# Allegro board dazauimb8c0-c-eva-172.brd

Outline 219.8 x 128 mm; copper layers: TOP, SGND, IN1, IN2, SVCC, IN3, SGND1, BOTTOM. Coordinates in mm from the lower left corner of the outline.

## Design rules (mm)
constraint set DEFAULT: min track width 0.102
net group W7-T123B: nets +3V_DEEP_SUS +VCCIN
net group W99-T123B: nets +3V_SSD +5VODD
net group DFP-S3.5W4(3.5)-T13B: nets M_B_CLKN0 M_B_CLKP0 PEX_TSTCLK PEX_TSTCLK# VMA_CLK0 VMA_CLK0# VMA_CLK1 VMA_CLK1# VMA_WCK01 VMA_WCK01# VMA_WCK23 VMA_WCK23# VMA_WCK45 VMA_WCK45# VMA_WCK67 VMA_WCK67#
net group DFP-S4.5W4(3.5)-T13B: nets C_IN_CLK C_IN_CLK# C_IN_CLK#_R C_IN_CLK_R C_TX0_HDMI+ C_TX0_HDMI+_R C_TX0_HDMI- C_TX0_HDMI-_R C_TX1_HDMI+ C_TX1_HDMI+_R C_TX1_HDMI- C_TX1_HDMI-_R C_TX2_HDMI+ C_TX2_HDMI+_R C_TX2_HDMI- C_TX2_HDMI-_R CLK_PCIE_LANN CLK_PCIE_LANP CLK_PCIE_SSDN CLK_PCIE_SSDN_C CLK_PCIE_SSDP CLK_PCIE_SSDP_C CLK_PCIE_WLANN CLK_PCIE_WLANP CLK_VGA_N CLK_VGA_P IN_CLK IN_CLK# IN_CLK#_R IN_CLK_R IN_D0 IN_D0# IN_D0#_R IN_D0_R IN_D1 IN_D1# IN_D1#_R IN_D1_R IN_D2 IN_D2# IN_D2#_R IN_D2_R INT_EDP_AUXN INT_EDP_AUXN_C INT_EDP_AUXP INT_EDP_AUXP_C INT_EDP_TXN0 INT_EDP_TXN0_C INT_EDP_TXN1 INT_EDP_TXN1_C INT_EDP_TXN2 INT_EDP_TXN2_C INT_EDP_TXN3 INT_EDP_TXN3_C INT_EDP_TXP0 INT_EDP_TXP0_C INT_EDP_TXP1 INT_EDP_TXP1_C INT_EDP_TXP2 INT_EDP_TXP2_C INT_EDP_TXP3 INT_EDP_TXP3_C INT_HDMICLK+_OUT INT_HDMICLK-_OUT INT_HDMITX0N_OUT INT_HDMITX0P_OUT INT_HDMITX1N_OUT INT_HDMITX1P_OUT INT_HDMITX2N_OUT INT_HDMITX2P_OUT M_A_CLKN0 M_A_CLKN1 M_A_CLKP0 M_A_CLKP1 M_B_DQSN0 M_B_DQSN1 M_B_DQSN2 M_B_DQSN3 M_B_DQSN4 M_B_DQSN5 M_B_DQSN6 M_B_DQSN7 M_B_DQSP0 M_B_DQSP1 M_B_DQSP2 M_B_DQSP3 M_B_DQSP4 M_B_DQSP5 M_B_DQSP6 M_B_DQSP7 PCIE_RCOMPN PCIE_RCOMPP PCIE_RXN9_LAN PCIE_RXN10_WLAN PCIE_RXN13_SSD PCIE_RXN13_SSD_C PCIE_RXN14_SSD PCIE_RXN14_SSD_C PCIE_RXN15_SSD PCIE_RXN15_SSD_C PCIE_RXN16_SSD PCIE_RXN16_SSD_C PCIE_RXN_LAN_L PCIE_RXP9_LAN PCIE_RXP10_WLAN PCIE_RXP13_SSD PCIE_RXP13_SSD_C PCIE_RXP14_SSD PCIE_RXP14_SSD_C PCIE_RXP15_SSD PCIE_RXP15_SSD_C PCIE_RXP16_SSD PCIE_RXP16_SSD_C PCIE_RXP_LAN_L PCIE_TXN9_LAN PCIE_TXN9_LAN_C PCIE_TXN10_WLAN PCIE_TXN10_WLAN_C PCIE_TXN13_SSD PCIE_TXN13_SSD_C PCIE_TXN14_SSD PCIE_TXN14_SSD_C PCIE_TXN15_SSD PCIE_TXN15_SSD_C PCIE_TXN16_SSD PCIE_TXN16_SSD_C PCIE_TXP9_LAN PCIE_TXP9_LAN_C PCIE_TXP10_WLAN PCIE_TXP10_WLAN_C PCIE_TXP13_SSD PCIE_TXP13_SSD_C PCIE_TXP14_SSD PCIE_TXP14_SSD_C PCIE_TXP15_SSD PCIE_TXP15_SSD_C PCIE_TXP16_SSD PCIE_TXP16_SSD_C PEG_RXN5 PEG_RXN5_C PEG_RXN6 PEG_RXN6_C PEG_RXN7 PEG_RXN7_C PEG_RXN8 PEG_RXN8_C PEG_RXP5 PEG_RXP5_C PEG_RXP6 PEG_RXP6_C PEG_RXP7 PEG_RXP7_C PEG_RXP8 PEG_RXP8_C PEG_TXN5 PEG_TXN5_C PEG_TXN6 PEG_TXN6_C PEG_TXN7 PEG_TXN7_C PEG_TXN8 PEG_TXN8_C PEG_TXP5 PEG_TXP5_C PEG_TXP6 PEG_TXP6_C PEG_TXP7 PEG_TXP7_C PEG_TXP8 PEG_TXP8_C SATA_RXN0_C SATA_RXN0_CN SATA_RXN0_HDD SATA_RXN0_IN SATA_RXN1A_C SATA_RXN1A_ODD SATA_RXN_OUT SATA_RXP0_C SATA_RXP0_CN SATA_RXP0_HDD SATA_RXP0_IN SATA_RXP1A_C SATA_RXP1A_ODD SATA_RXP_OUT SATA_TXN0_C SATA_TXN0_CN SATA_TXN0_HDD SATA_TXN0_IN SATA_TXN1A_C SATA_TXN1A_ODD SATA_TXN_OUT SATA_TXP0_C SATA_TXP0_CN SATA_TXP0_HDD SATA_TXP0_IN SATA_TXP1A_C SATA_TXP1A_ODD SATA_TXP_OUT TCRCOMP_DN TCRCOMP_DP USB3_SS0RX+ USB3_SS0RX- USB3_SS0TX+ USB3_SS0TX- USB30_RX1+ USB30_RX1+_C USB30_RX1- USB30_RX1-_C USB30_RX2+ USB30_RX2+_C USB30_RX2- USB30_RX2-_C USB30_RX3+ USB30_RX3- USB30_RX+_TYPEC1 USB30_RX+_TYPEC2 USB30_RX-_TYPEC1 USB30_RX-_TYPEC2 USB30_TX1+ USB30_TX1+_C USB30_TX1+_C_R USB30_TX1- USB30_TX1-_C USB30_TX1-_C_R USB30_TX2+ USB30_TX2+_C USB30_TX2+_C_R USB30_TX2- USB30_TX2-_C USB30_TX2-_C_R USB30_TX3+ USB30_TX3- USB30_TX+_TYPEC1 USB30_TX+_TYPEC1_C USB30_TX+_TYPEC2 USB30_TX+_TYPEC2_C USB30_TX-_TYPEC1 USB30_TX-_TYPEC1_C USB30_TX-_TYPEC2 USB30_TX-_TYPEC2_C USBP1+ USBP1+_C USBP1+_C_R USBP1+_C_R_N USBP1+_U14 USBP1- USBP1-_C USBP1-_C_R USBP1-_C_R_N USBP1-_U14 USBP2+ USBP2+_C USBP2- USBP2-_C USBP3+_TPC USBP3-_TPC USBP4+_DB USBP4-_DB USBP5+_CAM USBP5+_CAM_C USBP5-_CAM USBP5-_CAM_C USBP6+_CR USBP6-_CR USBP7+_FP USBP7-_FP USBP8+_TS USBP8-_TS USBP8_TS+_C USBP8_TS-_C USBP10+_BT USBP10-_BT USBP_TYPC+_C USBP_TYPC-_C
net group DFP-S4.54W4(3.5)-T13B: nets CNV_WR_CLK_DN CNV_WR_CLK_DP CNV_WR_LANE0_DN CNV_WR_LANE0_DP CNV_WR_LANE1_DN CNV_WR_LANE1_DP CNV_WT_CLK_DN CNV_WT_CLK_DP CNV_WT_LANE0_DN CNV_WT_LANE0_DP CNV_WT_LANE1_DN CNV_WT_LANE1_DP
net group DFP-S6W4(3.5)-T13B: nets M_A_DQSN0 M_A_DQSN1 M_A_DQSN2 M_A_DQSN3 M_A_DQSN4 M_A_DQSN5 M_A_DQSN6 M_A_DQSN7 M_A_DQSP0 M_A_DQSP1 M_A_DQSP2 M_A_DQSP3 M_A_DQSP4 M_A_DQSP5 M_A_DQSP6 M_A_DQSP7
net group DFP-S11.5(11: nets MDI0+ MDI0+_1 MDI0- MDI0-_1 MDI1+ MDI1+_1 MDI1- MDI1-_1 MDI2+ MDI2+_1 MDI2- MDI2-_1 MDI3+ MDI3+_1 MDI3- MDI3-_1
net group GND: nets GND
net group W4(3.5)-T13B: nets ACZ_BCLK ACZ_RST# ACZ_SDOUT ACZ_SYNC BIOS_WP# DDR4_DRAMRST# DDR_DRAMRST#_R DMIC_CLK DMIC_CLK_2 DMIC_CLK_2_R DMIC_CLK_L DMIC_DAT DMIC_DAT_2 DMIC_DAT_2_R DMIC_DAT_L DNBSWON# EC_PECI EC_PECR_R EC_PWROK H_CATERR# H_PROCHOT# HOLD# HWPG IMVP_PWRGD M_A_DQ0 M_A_DQ1 M_A_DQ2 M_A_DQ3 M_A_DQ4 M_A_DQ5 M_A_DQ6 M_A_DQ7 M_A_DQ8 M_A_DQ9 M_A_DQ10 M_A_DQ11 M_A_DQ12 M_A_DQ13 M_A_DQ14 M_A_DQ15 M_A_DQ16 M_A_DQ17 M_A_DQ18 M_A_DQ19 M_A_DQ20 M_A_DQ21 M_A_DQ22 M_A_DQ23 M_A_DQ24 M_A_DQ25 M_A_DQ26 M_A_DQ27 M_A_DQ28 M_A_DQ29 M_A_DQ30 M_A_DQ31 M_A_DQ32 M_A_DQ33 M_A_DQ34 M_A_DQ35 M_A_DQ36 M_A_DQ37 M_A_DQ38 M_A_DQ39 M_A_DQ40 M_A_DQ41 M_A_DQ42 M_A_DQ43 M_A_DQ44 M_A_DQ45 M_A_DQ46 M_A_DQ47 M_A_DQ48 M_A_DQ49 M_A_DQ50 M_A_DQ51 M_A_DQ52 M_A_DQ53 M_A_DQ54 M_A_DQ55 M_A_DQ56 M_A_DQ57 M_A_DQ58 M_A_DQ59 M_A_DQ60 M_A_DQ61 M_A_DQ62 M_A_DQ63 M_B_DQ0 M_B_DQ1 M_B_DQ2 M_B_DQ3 M_B_DQ4 M_B_DQ5 M_B_DQ6 M_B_DQ7 M_B_DQ8 M_B_DQ9 M_B_DQ10 M_B_DQ11 M_B_DQ12 M_B_DQ13 M_B_DQ14 M_B_DQ15 M_B_DQ16 M_B_DQ17 M_B_DQ18 M_B_DQ19 M_B_DQ20 M_B_DQ21 M_B_DQ22 M_B_DQ23 M_B_DQ24 M_B_DQ25 M_B_DQ26 M_B_DQ27 M_B_DQ28 M_B_DQ29 M_B_DQ30 M_B_DQ31 M_B_DQ32 M_B_DQ33 M_B_DQ34 M_B_DQ35 M_B_DQ36 M_B_DQ37 M_B_DQ38 M_B_DQ39 M_B_DQ40 M_B_DQ41 M_B_DQ42 M_B_DQ43 M_B_DQ44 M_B_DQ45 M_B_DQ46 M_B_DQ47 M_B_DQ48 M_B_DQ49 M_B_DQ50 M_B_DQ51 M_B_DQ52 M_B_DQ53 M_B_DQ54 M_B_DQ55 M_B_DQ56 M_B_DQ57 M_B_DQ58 M_B_DQ59 M_B_DQ60 M_B_DQ61 M_B_DQ62 M_B_DQ63 PCH_AZ_CODEC_BITCLK PCH_AZ_CODEC_RST# PCH_AZ_CODEC_SDIN0 PCH_AZ_CODEC_SDIN0_R PCH_AZ_CODEC_SDOUT PCH_AZ_CODEC_SYNC PCH_JTAGX PCH_SPI0_CLK PCH_SPI0_MISO PCH_SPI0_MOSI PCH_SPI1_CLK PCH_SPI1_CLK_R PCH_SPI1_SI PCH_SPI1_SI_R PCH_SPI1_SO PCH_SPI1_SO_R PCH_SPI_CS0# PCH_SPI_CS0#_R PCH_SPI_IO2 PCH_SPI_IO3 PCH_TCK PCH_TDI PCH_TDO PCH_TMS PCH_TRST# PEGX_RST# PEGX_RST#_C PEX_TERMP PLTRST# PROCHOT#_CPU PROCHOT_EC PROCPWRGD RSMRST# RT3612_VRHOT SPI_TPM_CS# SYS_PWROK SYS_RESET# TESTMODE USB_OC2# XDP_TCK XDP_TDI_CPU XDP_TDO_CPU XDP_TMS_CPU XDP_TRST#
net group W4(3.5)-T123B: nets 2ND_MBCLK 2ND_MBDATA 5V_HSMBCK 5V_HSMBDT 27M_XTAL_IN 27M_XTAL_OUT BRIGHT CNV_BRI_DT CNV_BRI_DT_R CNV_BRI_RSP CNV_BRI_RSP_L CNV_RGI_DT CNV_RGI_DT_R CNV_RGI_RSP CNV_RGI_RSP_L CPU_SVID_CLK CPU_SVID_DAT CPU_VIDALERT# DDCCLK_RIN DDCDATA_RIN DISP_ON ESPI_0 ESPI_0_R ESPI_1 ESPI_1_R ESPI_2 ESPI_2_R ESPI_3 ESPI_3_R ESPI_CLK ESPI_CLK_R ESPI_CS# ESPI_CS#_R ESPI_RESET# ESPI_RESET#_R GPUT_CLK_L GPUT_DATA_L H_VCCST_PWRGD HDMI_HPD HDMI_HPD_C HDMI_HPD_CON HDMI_MB_HPD_R HDMI_SCLK HDMI_SDATA MBP0# MBP1# MBP2# MBP3# MIPI60_CFG0# MIPI60_CFG1# MIPI60_CFG2# MIPI60_CFG3# MIPI60_CFG4# MIPI60_CFG5# MIPI60_CFG6# MIPI60_CFG7# MIPI60_CFG8# MIPI60_CFG9# MIPI60_CFG10# MIPI60_CFG11# MIPI60_CFG12# MIPI60_CFG13# MIPI60_CFG14# MIPI60_CFG15# MIPI60_CFG16_STB_DN MIPI60_CFG17_STB_DP MIPI60_CFG18_STB_DN MIPI60_CFG19_STB_DP PCH_BLON_C PCH_DISP_ON PCH_DPST_PWM PCH_LVDS_BLON PCIE_CLKREQ_LAN# PCIE_CLKREQ_SSD# PCIE_CLKREQ_VGA# PCIE_CLKREQ_WLAN# PM_THRMTRIP# PWM-VID RT3612_ALERT# RT3612_VCLK RT3612_VDIO RTC_RST# RTC_X1 RTC_X1_R RTC_X2 RTC_X2_R SDVO_CLK SDVO_DATA SMB_ML0_CLK SMB_ML0_DAT SMB_PCH_CLK SMB_PCH_DAT SMB_RUN_CLK SMB_RUN_DAT SRTC_RST# SUSCLK_32K SUSCLK_32KHZ SYS_SHDN# TP_I2C_CLK TP_I2C_DATA TP_SMB_CLK TP_SMB_DATA ULT_EDP_HPD ULT_EDP_HPD_R VCCAUX_VID0 VCCAUX_VID1 VCCSENSE VCCST_PWRGD VCCST_PWRGD_TCSS VGA_VCCSENSE VGA_VSSSENSE VR_SVID_ALERT# VR_SVID_CLK VR_SVID_DATA VSSSENSE XTAL_38P4M_IN XTAL_38P4M_IN_R XTAL_38P4M_OUT XTAL_38P4M_OUT_R
net group W4-T123B: nets +1.2VSUS
net group W5(4)-T13B: nets M_A_A0 M_A_A1 M_A_A2 M_A_A3 M_A_A4 M_A_A5 M_A_A6 M_A_A7 M_A_A8 M_A_A9 M_A_A10 M_A_A11 M_A_A12 M_A_A13 M_A_ACT# M_A_ALERT# M_A_BG#0 M_A_BG#1 M_A_BS#0 M_A_BS#1 M_A_CAS# M_A_CKE0 M_A_CKE1 M_A_CS#0 M_A_CS#1 M_A_DIM0_ODT0 M_A_DIM0_ODT1 M_A_PARITY M_A_RAS# M_A_WE# M_B_A0 M_B_A1 M_B_A2 M_B_A3 M_B_A4 M_B_A5 M_B_A6 M_B_A7 M_B_A8 M_B_A9 M_B_A10 M_B_A11 M_B_A12 M_B_A13 M_B_ACT# M_B_ALERT# M_B_BG#0 M_B_BG#1 M_B_BG#1_R M_B_BS#0 M_B_BS#1 M_B_CAS# M_B_CKE0 M_B_CS#0 M_B_DIM0_ODT0 M_B_PARITY M_B_RAS# M_B_WE#
net group W5(4.5: nets FBA_DBI0 FBA_DBI1 FBA_DBI2 FBA_DBI3 FBA_DBI4 FBA_DBI5 FBA_DBI6 FBA_DBI7 FBA_EDC0 FBA_EDC1 FBA_EDC2 FBA_EDC3 FBA_EDC4 FBA_EDC5 FBA_EDC6 FBA_EDC7 VMA_DQ0 VMA_DQ1 VMA_DQ2 VMA_DQ3 VMA_DQ4 VMA_DQ5 VMA_DQ6 VMA_DQ7 VMA_DQ8 VMA_DQ9 VMA_DQ10 VMA_DQ11 VMA_DQ12 VMA_DQ13 VMA_DQ14 VMA_DQ15 VMA_DQ16 VMA_DQ17 VMA_DQ18 VMA_DQ19 VMA_DQ20 VMA_DQ21 VMA_DQ22 VMA_DQ23 VMA_DQ24 VMA_DQ25 VMA_DQ26 VMA_DQ27 VMA_DQ28 VMA_DQ29 VMA_DQ30 VMA_DQ31 VMA_DQ32 VMA_DQ33 VMA_DQ34 VMA_DQ35 VMA_DQ36 VMA_DQ37 VMA_DQ38 VMA_DQ39 VMA_DQ40 VMA_DQ41 VMA_DQ42 VMA_DQ43 VMA_DQ44 VMA_DQ45 VMA_DQ46 VMA_DQ47 VMA_DQ48 VMA_DQ49 VMA_DQ50 VMA_DQ51 VMA_DQ52 VMA_DQ53 VMA_DQ54 VMA_DQ55 VMA_DQ56 VMA_DQ57 VMA_DQ58 VMA_DQ59 VMA_DQ60 VMA_DQ61 VMA_DQ62 VMA_DQ63
net group W6.5(6: nets FBA_CMD0 FBA_CMD1 FBA_CMD2 FBA_CMD3 FBA_CMD4 FBA_CMD5 FBA_CMD6 FBA_CMD7 FBA_CMD8 FBA_CMD9 FBA_CMD10 FBA_CMD11 FBA_CMD12 FBA_CMD13 FBA_CMD14 FBA_CMD15 FBA_CMD16 FBA_CMD17 FBA_CMD18 FBA_CMD19 FBA_CMD20 FBA_CMD21 FBA_CMD22 FBA_CMD23 FBA_CMD24 FBA_CMD25 FBA_CMD26 FBA_CMD27 FBA_CMD28 FBA_CMD29 FBA_CMD30 FBA_CMD31
net group W8-T123B: nets +1.05V_LAN +1.8V_DEEP_SUS +1.8V_SW +1V8_AON +3V +3V3_TPM +3V_LDO_EC +3V_S5 +3V_WLAN_P +3VPCU +3VPCU_EC +3VPCU_ECPLL +3VSPI +5V_PVDD +5VA +5VPCU +A3VPCU +AZA_VDD +G_SEN_PW +SMDDR_VREF_DIMM +USBPWR0 +VCC1.05_OUT_FET +VCCIO_OUT +VCCST +VCCSTG_TERM AVDD2 DVDD_IO
net group W10-T13B: nets CFG_RCOMP CNV_WT_RCOMP CPU_POPI_RCOMP CSI_RCOMP DP_RCOMP EMMC_RCOMP PCH_OPI_RCOMP SD3_RCOMP SNDW_RCOMP USB2_COMP
net group W10-T123B: nets +1.8V_S5 +1.35V_GFX +1V8_GFX_MAIN +3V_EC +FB_PLLAVDD +VDDQ_VTT +VGPU_CORE +VIN FB_CAL_PD_VDDQ NV_PLLVDD SP_PLLVDD VCCDSW_3P3
net group W12-T123B: nets +1.03_GFX +3V_RTC +3VLCD_CON_R_C +5V
net group W14-T123B: nets +2.5V_SUS
net group W15-T13B: nets CLK_BIASREF DDR_RCOMP0 DDR_RCOMP1 DDR_RCOMP2
net group W15-T123B: nets +VCC1.05_OUT_SFR_R +VCCDSW_1P05 +VCCIN_AUX +VCCLDOSTD_OUT_0P85 HP-L2 HP-L3 HP-R2 HP-R3 HP_JD# LINE1-L LINE1-R LINE1-VREFO-L LINE1-VREFO-R MIC2-VREFO SENSEA
net group W16-T123B: nets MEM_VREF_CTL_QA
net group W20-T123B: nets +1.2V_VCCPLL_OC +1.05V_EXT +3V_LAN +3V_RTC_0 +3V_RTC_1 +3V_RTC_2 +5V_HDMIC +SMDDR_VREF_DQ1_M1 +USBPWR1 +VCC1.05_OUT_PCH +VCC1.05_OUT_SFR +VCCDPHY_1P24 +VCCPFUSE_3P3 +VCCPLL_OC +VCCPRIM_3P3 +VCCRTC +VCCSTG +VNN_EXT FBA_VREFC_1 FBA_VREFC_2 PBA_PWR PBA_PWR_C PBA_PWR_R SM_VREF SMDDR_VREF_DQ1_M3 VCCA_CLKLDO_1V8 VCCSPI
net group W30-T123B: nets +VCCSTG_OUT_LGC
net group W40-T123B: nets +3VLCD_CON +3VLCD_CON_R +601_VCC +VCCFPGM +VCCSTG_OUT_FUSE L_SPK+ L_SPK+_1 L_SPK- L_SPK-_1 R_SPK+ R_SPK+_1 R_SPK- R_SPK-_1 RING2 SLEEVE VCC1P8A
net group W60-T123B: nets +1.05V_LAN_REGOUT
net group W80-T123B: nets +VIN_BLIGHT
nets with their own width: min track width 0.305; nets I2CA_SCL I2CA_SDA

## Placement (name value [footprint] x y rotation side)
C1  EV@220u/2V_7343H1.0  [CC7343]  110.25 123.56 180 top
C2  *EV@47U/6.3V_6  [C0603]  116.9 122.8 180 top
C3  EV@0.22u/10V_4  [C0402]  102.17 121.14 90 top
C4  EV@0.22u/10V_4  [C0402]  103.19 121.14 90 top
C5  *EV@47U/6.3V_6  [C0603]  116.9 121.14 0 top
C6  *EV@47U/6.3V_6  [C0603]  106.74 120.48 180 top
C7  *EV@47U/6.3V_6  [C0603]  110.3 120.48 0 top
C8  EV@47U/6.3V_6  [C0603]  116.9 119.49 180 top
C9  EV@0.22u/10V_4  [C0402]  101.03 119.24 90 top
C10  EV@0.22u/10V_4  [C0402]  102.04 119.24 90 top
C11  EV@0.22u/10V_4  [C0402]  103.31 119.24 90 top
C12  EV@0.22u/10V_4  [C0402]  104.33 119.24 90 top
C13  EV@47U/6.3V_6  [C0603]  110.3 119.06 180 top
C14  EV@47U/6.3V_6  [C0603]  106.74 118.96 0 top
C15  EV@10u/6.3V_4  [C0402]  137.35 117.46 180 top
C16  EV@1u/6.3V_4  [C0402]  134.68 117.21 180 top
C17  4.7u/25V_6  [C0603]  66.18 117.08 180 top
C18  EV@1u/6.3V_4  [C0402]  131.51 116.83 90 top
C19  *EV@22U/6.3V_6  [C0603]  140.83 116.62 270 top
C20  EV@22u/6.3V_6  [C0603]  142.25 116.62 270 top
C21  EV@1u/6.3V_4  [C0402]  134.94 115.18 180 top
C22  0.1u/16V_4  [C0402]  45.27 114.76 180 top
C23  10u/6.3V_6  [C0603]  47.48 114.51 0 top
C24  *0.1u/16V_4  [C0402]  50.23 114.41 0 top
C25  0.1u/16V_4  [C0402]  47.2 113.27 180 top
C26  EV@1u/6.3V_4  [C0402]  132.01 113.27 270 top
C27  EV@1u/6.3V_4  [C0402]  138.11 112.76 0 top
C28  0.1u/16V_4  [C0402]  56.25 112.38 270 top
C29  *0.1u/16V_4  [C0402]  47.2 112.25 180 top
C30  *4.7u/6.3V_4  [C0402_2]  41.82 112.33 270 top
C31  *4.7u/6.3V_4  [C0402_2]  40.6 111.85 270 top
C32  15p/50V_4  [C0402]  44.38 111.24 0 top
C33  15p/50V_4  [C0402]  46.19 111.24 0 top
C34  EV@1u/6.3V_4  [C0402]  110.25 110.88 270 top
C35  EV@1u/6.3V_4  [C0402]  101.28 110.86 270 top
C36  EV@0.22u/10V_4  [C0402]  98.11 110.81 180 top
C37  1000p/50V_4  [C0402]  56.25 110.6 90 top
C38  EV@1u/6.3V_4  [C0402]  111.26 110.58 270 top
C39  0.1u/16V_4  [C0402]  43.37 110.1 0 top
C40  EV@0.22u/10V_4  [C0402]  98.11 109.84 180 top
C41  EV@4.7u/6.3V_4  [C0402_2]  99.81 109.76 90 top
C42  0.1u/16V_4  [C0402]  41.29 109.46 0 top
C43  0.1u/16V_4  [C0402]  62.72 109.33 180 top
C44  EV@47U/6.3V_6  [C0603]  104.58 109.21 0 top
C45  0.1u/16V_4  [C0402]  43.37 109.08 0 top
C46  EV@1u/6.3V_4  [C0402]  109.03 109.08 90 top
C47  EV@10u/6.3V_4  [C0402]  139.38 109.08 270 top
C48  EV@4.7u/6.3V_4  [C0402_2]  110.55 108.83 180 top
C49  EV@1u/6.3V_4  [C0402]  134.68 108.83 90 top
C50  EV@1u/6.3V_4  [C0402]  102.68 108.7 90 top
C51  0.1u/16V_4  [C0402]  41.29 108.44 0 top
C52  EV@1u/6.3V_4  [C0402]  130.36 108.44 0 top
C53  0.1u/16V_4  [C0402]  62.72 108.06 180 top
C54  EV@0.1u/16V_4  [C0402]  99.76 107.99 270 top
C55  EV@10u/6.3V_4  [C0402]  105.6 107.94 0 top
C56  EV@1u/6.3V_4  [C0402]  107.5 107.73 0 top
C57  EV@4.7u/6.3V_4  [C0402_2]  98.59 107.68 270 top
C58  0.1u/16V_4  [C0402]  49.87 107.56 180 top
C59  *EV@10u/6.3V_4  [C0402]  89.85 107.56 180 top
C60  EV@10u/6.3V_4  [C0402]  100.77 107.43 270 top
C61  33p/50V_4  [C0402]  56.22 107.3 270 top
C62  0.1u/25V_4  [C0402]  60.03 107.1 0 top
C63  *EV@22U/6.3V_6  [C0603]  109.94 106.95 180 top
C64  0.1u/16V_4  [C0402]  40.12 106.56 270 top
C65  0.1u/16V_4  [C0402]  49.59 106.54 180 top
C66  EV@4.7u/6.3V_4  [C0402_2]  101.87 106.29 270 top
C67  1000p/50V_4  [C0402]  60.03 106.13 0 top
C68  EV@0.1u/16V_4  [C0402]  89.85 106.03 0 top
C69  EV@1u/6.3V_4  [C0402]  128.59 106.03 180 top
C70  EV@4.7u/6.3V_4  [C0402_2]  107 105.95 270 top
C71  EV@10u/6.3V_4  [C0402]  99.38 105.9 90 top
C72  EV@1u/6.3V_4  [C0402]  104.07 105.9 270 top
C73  EV@10u/6.3V_4  [C0402]  105.17 105.9 270 top
C74  EV@1u/6.3V_4  [C0402]  108.11 105.9 270 top
C75  EV@10u/6.3V_4  [C0402]  110.3 105.75 180 top
C76  EV@47U/6.3V_6  [C0603]  97.98 105.27 90 top
C77  EV@4.7u/6.3V_4  [C0402_2]  100.65 105.14 270 top
C78  EV@1u/6.3V_4  [C0402]  136.21 105.02 90 top
C79  EV@1u/6.3V_4  [C0402]  139.38 105.02 90 top
C80  EV@1u/6.3V_4  [C0402]  110.3 104.79 180 top
C81  EV@22u/6.3V_6  [C0603]  126.81 104.51 0 top
C82  EV@4.7u/6.3V_4  [C0402_2]  101.84 104.13 90 top
C83  EV@10u/6.3V_4  [C0402]  104.07 104.13 90 top
C84  EV@1u/6.3V_4  [C0402]  105.17 104.13 90 top
C85  EV@10u/6.3V_4  [C0402]  106.97 104.13 90 top
C86  EV@4.7u/6.3V_4  [C0402_2]  108.16 104.13 90 top
C87  EV@10u/6.3V_4  [C0402]  110.31 103.81 180 top
C88  0.1u/16V_4  [C0402]  48.58 103.62 180 top
C89  EV@4.7u/6.3V_4  [C0402_2]  89.09 103.49 180 top
C90  EV@0.1u/16V_4  [C0402]  100.1 103.33 0 top
C91  180p/50V_4  [C0402]  54.8 103.11 270 top
C92  EV@820p/50V_4  [C0402]  132.65 103.11 0 top
C93  1u/6.3V_4  [C0402]  40.45 102.81 270 top
C94  0.1u/16V_4  [C0402]  48.58 102.6 180 top
C95  EV@0.1u/16V_4  [C0402]  111.06 102.48 0 top
C96  EV@0.1u/16V_4  [C0402]  100.1 102.37 0 top
C97  0.01u/50V_4  [C0402]  29.53 102.35 180 top
C98  EV@4.7u/6.3V_4  [C0402_2]  101.84 102.35 270 top
C99  EV@1u/6.3V_4  [C0402]  104.07 102.35 270 top
C100  EV@10u/6.3V_4  [C0402]  105.17 102.35 270 top
C101  EV@10u/6.3V_4  [C0402]  106.97 102.35 270 top
C102  EV@4.7u/6.3V_4  [C0402_2]  108.16 102.35 270 top
C103  *EV@47U/6.3V_6  [C0603]  86.68 102.22 0 top
C104  EV@1u/6.3V_4  [C0402]  109.54 102.09 90 top
C105  *EV@22u/6.3V_4  [C0402_2]  98.87 101.28 0 top
C106  0.1u/16V_4  [C0402]  62.06 101.13 180 top
C107  EV@4.7u/6.3V_4  [C0402_2]  105.6 100.82 0 top
C108  EV@4.7u/6.3V_4  [C0402_2]  107.38 100.82 180 top
C109  EV@4.7u/6.3V_4  [C0402_2]  103.57 100.75 180 top
C110  EV@4.7u/6.3V_4  [C0402_2]  101.84 100.57 90 top
C111  EV@10u/6.3V_4  [C0402]  109.41 100.44 180 top
C112  *0.1u/25V_6  [C0603]  65.09 100.32 0 top
C113  *22U/6.3V_6  [C0603]  62.46 99.94 180 top
C114  EV@0.1u/16V_4  [C0402]  89.85 99.94 0 top
C115  EV@1u/6.3V_4  [C0402]  97.47 99.94 270 top
C116  EV@0.1u/16V_4  [C0402]  98.44 99.81 270 top
C117  EV@0.1u/16V_4  [C0402]  99.4 99.81 270 top
C118  EV@1u/6.3V_4  [C0402]  109.41 99.43 180 top
C119  1u/6.3V_4  [C0402]  31.05 99.17 270 top
C120  10u/6.3V_4  [C0402_2]  33.08 99.17 270 top
C121  1u/6.3V_4  [C0402]  34.61 99.17 270 top
C122  1u/6.3V_4  [C0402]  37.15 99.17 270 top
C123  1u/6.3V_4  [C0402]  39.18 99.17 270 top
C124  1u/6.3V_4  [C0402]  41.21 99.17 270 top
C125  0.022u/25V_4  [C0402]  53.45 99.17 180 top
C126  EV@1u/6.3V_4  [C0402]  107.06 99.17 90 top
C127  EV@22u/6.3V_6  [C0603]  103.97 98.82 90 top
C128  EV@0.1u/16V_4  [C0402]  100.52 98.61 270 top
C129  EV@1u/6.3V_4  [C0402]  101.48 98.61 270 top
C130  2.2u/6.3V_4  [C0402]  45.4 98.54 90 top
C131  0.047u/25V_4  [C0402]  46.42 98.54 270 top
C132  3.3p/50V_4  [C0402]  48.45 98.54 270 top
C133  EV@0.1u/16V_4  [C0402]  102.78 98.54 90 top
C134  EV@1u/6.3V_4  [C0402]  108.42 98.41 180 top
C135  EV@4.7u/6.3V_4  [C0402_2]  105.57 98.31 0 top
C136  EV@22u/6.3V_4  [C0402_2]  110.17 98.28 180 top
C137  EV@820p/50V_4  [C0402]  134.53 97.85 180 top
C138  EV@22u/6.3V_6  [C0603]  136.71 97.65 0 top
C139  EV@0.1u/16V_4  [C0402]  106.36 97.22 180 top
C140  10u/6.3V_4  [C0402]  51.37 96.89 270 top
C141  1u/6.3V_4  [C0402]  52.39 96.89 270 top
C142  1u/6.3V_4  [C0402]  61.02 96.89 180 top
C143  EV@4.7u/6.3V_4  [C0402_2]  100.39 96.86 90 top
C144  1u/6.3V_4  [C0402]  45.58 96.51 270 top
C145  0.01u/50V_4  [C0402]  46.54 96.51 90 top
C146  0.01u/50V_4  [C0402]  47.51 96.51 90 top
C147  68p/50V_4  [C0402]  48.47 96.51 90 top
C148  1u/6.3V_4  [C0402]  49.44 96.51 270 top
C149  1u/6.3V_4  [C0402]  50.4 96.51 270 top
C150  1u/6.3V_4  [C0402]  61.02 95.87 180 top
C151  EV@22u/6.3V_6  [C0603]  136.71 95.74 0 top
C152  10u/6.3V_4  [C0402]  56.96 95.24 0 top
C153  2.2u/10V_4  [C0402]  54.67 95.11 180 top
C154  1u/6.3V_4  [C0402]  58.35 94.86 90 top
C155  1u/6.3V_4  [C0402]  59.37 94.86 90 top
C156  10u/6.3V_4  [C0402]  61.02 94.86 180 top
C157  EV@1u/6.3V_4  [C0402]  121.85 94.32 90 top
C158  EV@1u/6.3V_4  [C0402]  123.2 94.32 90 top
C159  0.1u/6.3V_2  [C0201]  54.29 94.22 0 top
C160  EV@1u/6.3V_4  [C0402]  139.89 93.59 0 top
C161  10u/6.3V_4  [C0402]  50.23 93.46 0 top
C162  1u/6.3V_4  [C0402]  26.86 92.7 0 top
C163  EV@1u/6.3V_4  [C0402]  130.62 92.19 270 top
C164  1u/6.3V_4  [C0402]  50.35 92.06 270 top
C165  EV@10u/6.3V_4  [C0402]  128.59 90.92 180 top
C166  EV@1u/6.3V_4  [C0402]  132.04 90.79 270 top
C167  1u/6.3V_4  [C0402]  26.86 90.28 0 top
C168  EV@10u/6.3V_4  [C0402]  136.46 90.28 0 top
C169  10u/6.3V_4  [C0402_2]  26.86 88.89 0 top
C170  0.01u/50V_4  [C0402]  28.89 88.25 90 top
C171  10u/6.3V_4  [C0402]  50.35 88 180 top
C172  EV@1u/6.3V_4  [C0402]  138.87 86.85 0 top
C173  1u/6.3V_4  [C0402]  26.86 86.73 0 top
C174  EV@1u/6.3V_4  [C0402]  127.57 86.73 270 top
C175  EV@1u/6.3V_4  [C0402]  130.74 86.73 90 top
C176  3.3p/50V_4  [C0402]  30.67 86.47 270 top
C177  22U/6.3V_6  [C0603]  85.66 86.22 270 top
C178  1u/6.3V_4  [C0402]  50.23 85.97 180 top
C179  47U/6.3V_6  [C0603]  89.22 85.1 180 top
C180  *HDMI_R@0.1u/16V_4  [C0402]  24.06 84.31 270 top
C181  *HDMI_R@0.1u/16V_4  [C0402]  25.08 84.31 270 top
C182  HDMI_R@0.1u/16V_4  [C0402]  26.1 84.31 270 top
C183  220p/50V_4  [C0402]  14.92 83.93 180 top
C184  1u/6.3V_4  [C0402]  50.28 83.86 180 top
C185  47U/6.3V_6  [C0603]  89.22 83.68 180 top
C186  HDMI_R@0.1u/16V_4  [C0402]  23.56 82.66 0 top
C187  HDMI_R@0.1u/10V_2  [C0201]  25.77 81.77 180 top
C188  0.1u/16V_4  [C0402]  50.35 81.77 0 top
C189  0.047u/25V_4  [C0402]  37.65 81.27 180 top
C190  68p/50V_4  [C0402]  39.43 81.27 0 top
C191  1u/6.3V_4  [C0402]  41.21 81.27 180 top
C192  68p/50V_4  [C0402]  46.67 81.27 180 top
C193  1u/6.3V_4  [C0402]  48.45 81.27 180 top
C194  1u/6.3V_4  [C0402]  29.48 80.68 90 top
C195  1u/6.3V_4  [C0402]  30.44 80.68 90 top
C196  HDMI_R@0.1u/10V_2  [C0201]  25.77 80.63 180 top
C197  HDMI_R@0.1u/10V_2  [C0201]  25.77 79.87 180 top
C198  HDMI_R@0.1u/10V_2  [C0201]  25.77 78.73 180 top
C199  1u/6.3V_4  [C0402]  30.67 78.29 90 top
C200  HDMI_R@0.1u/10V_2  [C0201]  25.77 77.96 180 top
C201  HDMI_R@0.1u/10V_2  [C0201]  25.77 76.82 180 top
C202  1U/6.3V_4  [C0402]  100.49 76.16 180 top
C203  HDMI_R@0.1u/10V_2  [C0201]  25.77 76.06 180 top
C204  10u/6.3V_4  [C0402]  56.83 75.93 180 top
C205  HDMI_R@0.1u/16V_4  [C0402]  18.1 74.92 180 top
C206  HDMI_R@0.1u/10V_2  [C0201]  25.77 74.92 180 top
C207  1U/6.3V_4  [C0402]  100.6 74.76 180 top
C208  0.1u/6.3V_2  [C0201]  55.21 74.41 270 top
C209  2.2u/10V_4  [C0402]  58.1 74.28 90 top
C210  HDMI_R@0.1u/16V_4  [C0402]  26.22 74.08 180 top
C211  0.022u/25V_4  [C0402]  63.18 73.65 270 top
C212  HDMI_R@0.1u/16V_4  [C0402]  26.22 73.11 180 top
C213  10u/6.3V_4  [C0402]  50.23 72.5 180 top
C214  10u/6.3V_4  [C0402_2]  30.16 72 0 top
C215  1U/6.3V_4  [C0402]  81.98 71.3 0 top
C216  0.01u/50V_4  [C0402]  50.23 70.85 0 top
C217  68p/50V_4  [C0402]  30.16 70.47 180 top
C218  *15P/25V_2  [C0201]  85.33 70.29 180 top
C219  3.3p/50V_4  [C0402]  50.23 69.46 0 top
C220  10u/6.3V_4  [C0402_2]  30.16 69.33 0 top
C221  22U/6.3V_6  [C0603]  85.51 69.05 0 top
C222  *HDMI_R@0.1u/16V_4  [C0402]  25.33 68.57 180 top
C223  22U/6.3V_6  [C0603]  82.87 68.45 0 top
C224  10u/6.3V_4  [C0402]  50.23 68.44 180 top
C225  0.01u/50V_4  [C0402]  36.26 67.93 180 top
C226  0.01u/50V_4  [C0402]  38.16 67.93 0 top
C227  1u/6.3V_4  [C0402]  40.07 67.93 180 top
C228  1u/6.3V_4  [C0402]  46.04 67.93 0 top
C229  47U/6.3V_6  [C0603]  85.51 67.61 0 top
C230  22U/6.3V_6  [C0603]  87.69 67.04 90 top
C231  22U/6.3V_6  [C0603]  82.87 67.03 0 top
C232  1U/6.3V_4  [C0402]  88.89 66.66 90 top
C233  1U/6.3V_4  [C0402]  85.79 66.41 0 top
C234  *15P/25V_2  [C0201]  89.72 66.41 270 top
C235  10u/6.3V_4  [C0402]  50.23 65.9 180 top
C236  10U/6.3V_6  [C0603]  82.87 65.59 0 top
C237  47U/6.3V_6  [C0603]  85.33 64.6 90 top
C238  1u/6.3V_4  [C0402]  50.23 64.5 180 top
C239  *10p/50V_4  [C0402]  22.67 64.38 270 top
C240  *15P/25V_2  [C0201]  92.09 64.22 90 top
C241  22U/6.3V_6  [C0603]  82.87 64.17 0 top
C242  22U/6.3V_6  [C0603]  86.75 64.15 90 top
C243  22U/6.3V_6  [C0603]  88.17 64.15 90 top
C244  47U/6.3V_6  [C0603]  89.6 64.15 90 top
C245  22U/6.3V_6  [C0603]  91.02 64.15 90 top
C246  1u/6.3V_4  [C0402]  50.1 62.98 180 top
C247  10U/6.3V_6  [C0603]  82.87 62.75 0 top
C248  10U/10V_4  [C0402_2]  85.05 62.67 180 top
C249  *10p/50V_4  [C0402]  22.67 62.6 90 top
C250  10U/10V_4  [C0402_2]  93.89 62.19 0 top
C251  1u/6.3V_4  [C0402]  43.62 61.45 0 top
C252  1u/6.3V_4  [C0402]  45.65 61.45 0 top
C253  10U/10V_4  [C0402_2]  85.05 61.45 180 top
C254  22U/6.3V_6  [C0603]  89.29 61.43 270 top
C255  22U/6.3V_6  [C0603]  90.7 61.41 270 top
C256  22U/6.3V_6  [C0603]  87.23 61.38 0 top
C257  1u/6.3V_4  [C0402]  34.35 61.33 0 top
C258  0.047u/25V_4  [C0402]  36.13 61.33 180 top
C259  0.047u/25V_4  [C0402]  37.91 61.33 0 top
C260  1u/6.3V_4  [C0402]  40.04 61.33 180 top
C261  1u/6.3V_4  [C0402]  50.23 61.33 180 top
C262  10U/6.3V_6  [C0603]  82.87 61.33 0 top
C263  10U/10V_4  [C0402_2]  92.01 61 270 top
C264  10U/10V_4  [C0402_2]  93.86 61 0 top
C265  10U/10V_4  [C0402_2]  85.05 60.26 180 top
C266  1U/6.3V_4  [C0402]  82.82 60.13 0 top
C267  1U/6.3V_4  [C0402]  50.23 59.93 0 top
C268  10u/6.3V_4  [C0402_2]  30.19 59.83 0 top
C269  47U/6.3V_6  [C0603]  87.23 59.83 0 top
C270  *1.6p/50V_4  [C0402]  22.16 59.04 270 top
C271  22U/6.3V_6  [C0603]  83.35 58.94 180 top
C272  0.1u/16V_4  [C0402]  25.72 58.66 0 top
C273  *15P/25V_2  [C0201]  85.15 58.53 180 top
C274  1U/6.3V_4  [C0402]  50.23 58.41 0 top
C275  47U/6.3V_6  [C0603]  87.01 58.41 0 top
C276  *15P/25V_2  [C0201]  85.18 57.8 180 top
C277  0.1u/16V_4  [C0402]  25.72 57.64 0 top
C278  *1U/6.3V_4  [C0402]  96.53 57.57 270 top
C279  47U/6.3V_6  [C0603]  83.35 57.39 180 top
C280  *1.6p/50V_4  [C0402]  22.16 57.26 90 top
C281  1u/6.3V_4  [C0402]  50.23 57.14 180 top
C282  10U/6.3V_6  [C0603]  95.31 57.11 90 top
C283  *15P/25V_2  [C0201]  85.16 57.07 180 top
C284  47U/6.3V_6  [C0603]  87.01 56.98 0 top
C285  *15P/25V_2  [C0201]  85.16 56.31 180 top
C286  22U/6.3V_6  [C0603]  83.32 55.87 180 top
C287  *1.6p/50V_4  [C0402]  23.35 55.74 90 top
C288  22U/6.3V_6  [C0603]  87.31 55.56 0 top
C289  *15P/25V_2  [C0201]  85.16 55.42 180 top
C290  22U/6.3V_6  [C0603]  90.56 55.13 0 top
C291  *15P/25V_2  [C0201]  85.16 54.66 180 top
C292  22U/6.3V_6  [C0603]  83.35 54.41 180 top
C293  *0.1u/6.3V_2  [C0201]  53.57 54.34 90 top
C294  22U/6.3V_6  [C0603]  87.79 54.14 0 top
C295  *1.6p/50V_4  [C0402]  23.35 53.96 270 top
C296  47U/6.3V_6  [C0603]  90.56 53.71 0 top
C297  10U/10V_4  [C0402_2]  84.9 53.1 180 top
C298  *15P/25V_2  [C0201]  83.51 52.88 0 top
C299  22U/6.3V_6  [C0603]  87.79 52.72 0 top
C300  *15P/25V_2  [C0201]  89.88 52.63 180 top
C301  *15P/25V_2  [C0201]  89.88 51.92 180 top
C302  10U/10V_4  [C0402_2]  84.9 51.9 180 top
C303  1u/6.3V_4  [C0402]  30.16 51.52 0 top
C304  TPC@0.1u/16V_4  [C0402]  17.05 51.47 180 top
C305  22U/6.3V_6  [C0603]  87.79 51.29 0 top
C306  *15P/25V_2  [C0201]  89.88 51.2 180 top
C307  22U/6.3V_6  [C0603]  83.15 50.81 90 top
C308  10U/10V_4  [C0402_2]  84.9 50.71 180 top
C309  68p/50V_4  [C0402]  30.16 50.56 180 top
C310  TPC@470p/50V_4  [C0402]  17.05 50.46 180 top
C311  47U/6.3V_6  [C0603]  87.21 49.87 0 top
C312  1u/6.3V_4  [C0402]  30.16 49.59 0 top
C313  10U/10V_4  [C0402_2]  84.87 49.52 180 top
C314  1u/6.3V_4  [C0402]  30.16 48.63 0 top
C315  10U/10V_4  [C0402]  84.9 48.42 180 top
C316  *1U/6.3V_4  [C0402]  77.91 48.3 90 top
C317  1U/6.3V_4  [C0402]  78.9 48.3 270 top
C318  2200p/50V_4  [C0402]  35.49 48.12 180 top
C319  0.1u/16V_4  [C0402]  37.27 48.12 180 top
C320  1u/6.3V_4  [C0402]  39.05 48.12 0 top
C321  1u/6.3V_4  [C0402]  44.38 48.12 0 top
C322  2200p/50V_4  [C0402]  46.16 48.12 0 top
C323  100p/50V_4  [C0402]  215.38 47.53 0 top
C324  1u/6.3V_4  [C0402]  50.23 47.48 180 top
C325  10U/10V_4  [C0402_2]  84.85 47.33 180 top
C326  *10P/50V_2  [C0201]  63.74 46.98 90 top
C327  100p/50V_4  [C0402]  215.38 46.19 0 top
C328  TPC@1u/10V_4  [C0402]  17.08 45.71 0 top
C329  0.1u/16V_2  [C0201]  77.28 45.22 90 top
C330  1U/6.3V_4  [C0402]  53.15 44.94 180 top
C331  10U/10V_4  [C0402_2]  99.5 44.06 0 top
C332  100p/50V_4  [C0402]  215.76 43.83 270 top
C333  4.7u/6.3V_6  [C0603]  211.14 43.8 270 top
C334  4.7u/6.3V_6  [C0603]  209.64 43.78 270 top
C335  10U/10V_4  [C0402_2]  103.57 43.6 270 top
C336  10U/10V_4  [C0402_2]  104.79 43.6 270 top
C337  10U/10V_4  [C0402_2]  102.33 43.58 270 top
C338  1U/6.3V_4  [C0402]  79.84 42.81 90 top
C339  *1U/6.3V_4  [C0402]  100.21 42.81 0 top
C340  100p/50V_4  [C0402]  215.78 42.1 270 top
C341  *1U/6.3V_4  [C0402]  101.66 41.52 90 top
C342  *1U/6.3V_4  [C0402]  96.58 40.63 90 top
C343  *1000p/50V_4  [C0402]  210.63 39.86 180 top
C344  0.1u/16V_2  [C0201]  66.48 38.98 90 top
C345  *1.6p/50V_4  [C0402]  21.27 38.34 270 top
C346  1u/6.3V_4  [C0402]  30.16 38.34 0 top
C347  *0.1u/16V_4  [C0402]  108.24 38.09 270 top
C348  1u/6.3V_4  [C0402]  49.9 38.04 270 top
C349  0.1u/16V_4  [C0402]  24.45 37.96 0 top
C350  10u/6.3V_4  [C0402_2]  30.16 37.2 0 top
C351  0.1u/16V_4  [C0402]  24.45 36.94 0 top
C352  *1.6p/50V_4  [C0402]  21.27 36.56 90 top
C353  *0.1u/10V_2  [C0201]  66.36 36.31 180 top
C354  *1U/6.3V_4  [C0402]  51.62 35.8 180 top
C355  10u/6.3V_4  [C0402_2]  37.91 34.78 0 top
C356  10u/6.3V_4  [C0402_2]  43.37 34.78 0 top
C357  68p/50V_4  [C0402]  45.15 34.78 0 top
C358  10u/6.3V_4  [C0402_2]  30.8 34.53 90 top
C359  1u/6.3V_4  [C0402]  31.94 34.53 90 top
C360  68p/50V_4  [C0402]  32.95 34.53 270 top
C361  *0.1u/6.3V_2  [C0201]  50.51 34.43 0 top
C362  *0.1u/16V_4  [C0402]  110.17 34.15 0 top
C363  *1.6p/50V_4  [C0402]  23.56 33.51 90 top
C364  0.1u/10V_2  [C0201]  187.01 32.24 90 top
C365  0.1u/10V_2  [C0201]  191.45 32.24 90 top
C366  *0.1u/16V_4  [C0402]  200.21 32.07 0 top
C367  180p/50V_4  [C0402]  196.2 31.86 90 top
C368  *1.6p/50V_4  [C0402]  23.56 31.74 270 top
C369  *0.1u/6.3V_2  [C0201]  47.18 31.74 180 top
C370  0.1u/16V_2  [C0201]  164.37 31.63 0 top
C371  180p/50V_4  [C0402]  182.69 31.48 0 top
C372  0.1u/10V_2  [C0201]  183.96 31.48 270 top
C373  22p/50V_4  [C0402]  158.99 31.3 0 top
C374  1u/6.3V_2  [C0201]  164.37 30.87 180 top
C375  *10u/6.3V_6  [C0603]  199.81 30.87 180 top
C376  *10u/6.3V_4  [C0402_2]  46.67 30.72 0 top
C377  *1u/10V_4  [C0402]  210.73 30.39 180 top
C378  *0.1u/16V_4  [C0402]  206.54 30.24 180 top
C379  *10u/6.3V_6  [C0603]  204.35 30.03 180 top
C380  *0.1u/16V_4  [C0402]  48.07 29.83 270 top
C381  180p/50V_4  [C0402]  182.31 29.58 270 top
C382  *0.1u/16V_4  [C0402]  158.05 29.2 0 top
C383  *15p/50V_4  [C0402]  81.85 28.64 0 top
C384  180p/50V_4  [C0402]  201 27.65 180 top
C385  10u/6.3V_4  [C0402_2]  203.88 27.49 90 top
C386  0.1u/10V_2  [C0201]  200.49 26.66 270 top
C387  180p/50V_4  [C0402]  201.59 23.99 0 top
C388  0.1u/10V_2  [C0201]  181.29 23.48 180 top
C389  *10p/50V_4  [C0402]  178.98 23.05 180 top
C390  180p/50V_4  [C0402]  201.61 22.97 180 top
C391  TPM@10u/6.3V_6  [C0603]  130.44 22.47 270 top
C392  TPM@0.1u/10V_2  [C0201]  131.51 22.34 90 top
C393  *PBA@0.01u/50V_4  [C0402]  50.53 22.24 180 top
C394  220p/25V_2  [C0201]  149.9 22.21 0 top
C395  GS@0.1u/10V_2  [C0201]  58.23 21.83 0 top
C396  1000p/50V_4  [C0402]  115.76 21.47 270 top
C397  1000p/50V_4  [C0402]  116.72 21.47 270 top
C398  1000p/50V_4  [C0402]  117.74 21.47 270 top
C399  1000p/50V_4  [C0402]  118.73 21.47 270 top
C400  220p/25V_2  [C0201]  149.9 20.94 0 top
C401  220p/25V_2  [C0201]  171 20.89 270 top
C402  220p/25V_2  [C0201]  171.72 20.89 270 top
C403  220p/25V_2  [C0201]  172.43 20.89 270 top
C404  220p/25V_2  [C0201]  169.48 20.86 270 top
C405  220p/25V_2  [C0201]  170.22 20.86 270 top
C406  220p/25V_2  [C0201]  167.96 20.69 270 top
C407  220p/25V_2  [C0201]  150.81 20.53 90 top
C408  220p/25V_2  [C0201]  151.57 20.53 90 top
C409  220p/25V_2  [C0201]  152.33 20.53 90 top
C410  220p/25V_2  [C0201]  153.1 20.53 90 top
C411  220p/25V_2  [C0201]  153.86 20.53 90 top
C412  220p/25V_2  [C0201]  166.43 20.43 270 top
C413  TPM@0.1u/10V_2  [C0201]  121.58 20.41 180 top
C414  220p/25V_2  [C0201]  155.48 20.18 90 top
C415  220p/25V_2  [C0201]  156.2 20.18 90 top
C416  220p/25V_2  [C0201]  156.93 20.18 90 top
C417  220p/25V_2  [C0201]  157.64 20.18 90 top
C418  220p/25V_2  [C0201]  158.35 20.15 90 top
C419  220p/25V_2  [C0201]  159.07 20.15 90 top
C420  220p/25V_2  [C0201]  159.78 20.15 90 top
C421  220p/25V_2  [C0201]  160.49 20.15 90 top
C422  220p/25V_2  [C0201]  161.2 20.15 90 top
C423  220p/25V_2  [C0201]  161.91 20.15 90 top
C424  220p/25V_2  [C0201]  168.69 20.08 90 top
C425  *PBA@2.2u/16V_6  [C0603]  46.67 20.05 180 top
C426  TPC@0.1u/25V_4  [C0402]  9.99 20.03 0 top
C427  220p/25V_2  [C0201]  167.19 19.93 90 top
C428  HDD_R@0.01u/10V_2  [C0201]  209.1 19.93 90 top
C429  HDD_R@0.01u/10V_2  [C0201]  210.37 19.93 90 top
C430  HDD_R@0.01u/10V_2  [C0201]  211.14 19.93 90 top
C431  HDD_R@0.01u/10V_2  [C0201]  212.51 19.93 90 top
C432  TPM@0.1u/10V_2  [C0201]  121.58 19.7 180 top
C433  0.1u/16V_4  [C0402]  200.65 19.67 270 top
C434  1000p/50V_4  [C0402]  201.61 19.67 90 top
C435  1u/6.3V_4  [C0402]  178.4 19.49 0 top
C436  GS@10u/6.3V_4  [C0402_2]  60.01 19.16 90 top
C437  180p/50V_4  [C0402]  181.27 18.88 0 top
C438  *TPC@390p/50V_4  [C0402]  11.36 18.4 0 top
C439  *10p/50V_4  [C0402]  72.83 18.4 180 top
C440  0.1u/16V_4  [C0402]  178.57 18.15 90 top
C441  TPC@0.1u/16V_4  [C0402]  27.75 18.02 270 top
C442  0.1u/10V_2  [C0201]  180.91 17.79 270 top
C443  0.1u/10V_2  [C0201]  181.67 17.79 270 top
C444  TPC@0.1u/25V_4  [C0402]  20.41 17.69 90 top
C445  TPM@0.1u/10V_2  [C0201]  129.45 17.64 270 top
C446  TPM@10u/6.3V_6  [C0603]  130.52 17.51 90 top
C447  GS@0.1u/10V_2  [C0201]  59.88 17.13 90 top
C448  *0.1u/6.3V_2  [C0201]  58.23 16.62 0 top
C449  HDD_R@0.1u/10V_2  [C0201]  214.31 16.37 270 top
C450  HDD_R@0.1u/10V_2  [C0201]  215.07 16.37 270 top
C451  HDD_R@0.1u/10V_2  [C0201]  215.83 16.37 270 top
C452  TPC@0.1u/25V_4  [C0402]  15.4 16.12 90 top
C453  100p/50V_4  [C0402]  201.86 16.12 0 top
C454  0.1u/16V_4  [C0402]  214.56 15.35 0 top
C455  PBA@0.01u/50V_4  [C0402]  49.34 14.59 270 top
C456  PBA@4.7u/6.3V_4  [C0402_2]  50.43 14.59 270 top
C457  10u/6.3V_6  [C0603]  201.74 14.46 0 top
C458  TPC@22u/6.3V_6  [C0603]  27.95 14.34 90 top
C459  TPC@22u/6.3V_6  [C0603]  29.4 14.34 90 top
C460  *10p/50V_4  [C0402]  71.56 14.34 90 top
C461  10u/6.3V_4  [C0402_2]  214.56 14.21 0 top
C462  TPC@0.1u/25V_4  [C0402]  10.22 13.45 270 top
C463  *0.1u/16V_4  [C0402]  57.34 13.07 90 top
C464  GS@33p/50V_4  [C0402]  69.15 12.94 90 top
C465  *10u/6.3V_4  [C0402_2]  214.56 12.94 0 top
C466  HDD_R@0.1u/10V_2  [C0201]  208.5 12.81 0 top
C467  GS@33p/50V_4  [C0402]  63.82 12.56 0 top
C468  HDD_R@0.01u/10V_2  [C0201]  209.61 12.56 90 top
C469  HDD_R@0.01u/10V_2  [C0201]  210.88 12.56 90 top
C470  HDD_R@0.01u/10V_2  [C0201]  211.77 12.56 90 top
C471  HDD_R@0.01u/10V_2  [C0201]  213.04 12.56 90 top
C472  HDD_N@0.01u/10V_2  [C0201]  209.61 12.11 270 top
C473  HDD_N@0.01u/10V_2  [C0201]  210.88 12.11 270 top
C474  HDD_N@0.01u/10V_2  [C0201]  211.77 12.11 270 top
C475  HDD_N@0.01u/10V_2  [C0201]  213.04 12.11 270 top
C476  HDD_R@0.1u/10V_2  [C0201]  208.47 12.1 0 top
C477  0.1u/10V_2  [C0201]  191.32 11.67 270 top
C478  0.1u/10V_2  [C0201]  192.09 11.67 270 top
C479  HDD_R@10u/6.3V_4  [C0402_2]  208.06 11.14 180 top
C480  180p/50V_4  [C0402]  198.94 11.04 0 top
C481  SSD@0.22u/10V_4  [C0402]  30.54 9.64 90 top
C482  SSD@0.22u/10V_4  [C0402]  31.56 9.64 90 top
C483  SSD@0.22u/10V_4  [C0402]  32.95 9.64 90 top
C484  SSD@0.22u/10V_4  [C0402]  33.97 9.64 90 top
C485  SSD@0.22u/10V_4  [C0402]  34.99 9.64 90 top
C486  SSD@0.22u/10V_4  [C0402]  36 9.64 90 top
C487  SSD@0.22u/10V_4  [C0402]  27.62 9.38 90 top
C488  SSD@0.22u/10V_4  [C0402]  28.64 9.38 90 top
C489  *SSD@0.1u/16V_2  [C0201]  23.18 4.43 180 top
C490  SSD@0.1u/16V_2  [C0201]  36.26 4.43 270 top
C491  *SSD@0.1u/16V_2  [C0201]  38.92 4.43 270 top
C492  *TPC@0.1u/25V_4  [C0402]  11.62 3.03 270 top
C493  *EV@0.1u/16V_4  [C0402]  100.26 125.34 0 bottom
C494  *EV@10u/6.3V_4  [C0402]  116.52 124.7 0 bottom
C495  EV@0.1u/16V_4  [C0402]  101.81 124.14 90 bottom
C496  *EV@10u/6.3V_4  [C0402]  116.52 123.68 0 bottom
C497  EV@22U/6.3VS_4  [C0402]  117.54 122.54 180 bottom
C498  *0.1u/6.3V_2  [C0201]  39.61 122.34 90 bottom
C499  EV@10u/6.3V_4  [C0402]  117.16 121.53 180 bottom
C500  EV@10u/6.3V_4  [C0402]  118.93 121.53 0 bottom
C501  EV@0.1u/16V_4  [C0402]  98.21 121.45 180 bottom
C502  EV@22u/6.3V_6  [C0603]  127.52 120.53 270 bottom
C503  EV@4.7u/6.3V_4  [C0402_2]  117.16 120.43 180 bottom
C504  EV@4.7u/6.3V_4  [C0402_2]  119.24 120.43 0 bottom
C505  EV@22u/6.3V_6  [C0603]  108.01 120.38 180 bottom
C506  EV@47U/6.3V_6  [C0603]  111.06 120.38 0 bottom
C507  EV@4.7u/6.3V_4  [C0402_2]  113.35 120.38 180 bottom
C508  0.1u/16V_4  [C0402]  39.64 119.21 90 bottom
C509  EV@47U/6.3V_6  [C0603]  103.72 119.09 180 bottom
C510  EV@4.7u/6.3V_4  [C0402_2]  106.87 118.99 0 bottom
C511  EV@4.7u/6.3V_4  [C0402_2]  113.35 118.96 180 bottom
C512  EV@4.7u/6.3V_4  [C0402_2]  109.49 118.88 180 bottom
C513  EV@4.7u/6.3V_4  [C0402_2]  111.29 118.48 0 bottom
C514  EV@22U/6.3VS_4  [C0402]  118.3 118.22 90 bottom
C515  EV@10u/6.3V_4  [C0402]  119.31 118.22 90 bottom
C516  EV@10u/6.3V_4  [C0402]  120.33 118.22 90 bottom
C517  *EV@10u/6.3V_4  [C0402]  106.87 117.84 0 bottom
C518  EV@22u/6.3V_6  [C0603]  123 117.82 0 bottom
C519  EV@10u/6.3V_4  [C0402]  109.49 117.74 180 bottom
C520  EV@4.7u/6.3V_4  [C0402_2]  120.58 116.7 0 bottom
C521  *EV@22U/6.3V_6  [C0603]  123 116.32 0 bottom
C522  *EV@47U/6.3V_6  [C0603]  90.05 115.94 180 bottom
C523  EV@4.7u/6.3V_4  [C0402_2]  120.58 115.43 0 bottom
C524  EV@22u/6.3V_6  [C0603]  123 114.79 0 bottom
C525  10p/3KV_1808  [CC1808]  21.4 112.51 234 bottom
C526  0.1u/25V_4  [C0402]  66.86 106.29 90 bottom
C527  0.01u/50V_4  [C0402]  67.88 106.29 90 bottom
C528  10P/50V_4  [C0402]  41.34 105.4 270 bottom
C529  10P/50V_4  [C0402]  42.48 105.4 270 bottom
C530  0.1u/16V_4  [C0402]  48.19 105.29 90 bottom
C531  0.1u/16V_4  [C0402]  49.21 105.29 90 bottom
C532  180p/50V_4  [C0402]  57.19 104.79 270 bottom
C533  0.1u/16V_4  [C0402]  50.23 104.38 90 bottom
C534  0.1u/16V_4  [C0402]  51.24 104.38 90 bottom
C535  0.1u/16V_4  [C0402]  52.21 104.38 90 bottom
C536  0.1u/16V_4  [C0402]  53.22 104.38 90 bottom
C537  0.1u/16V_4  [C0402]  54.19 104.38 90 bottom
C538  0.1u/16V_4  [C0402]  55.21 104.38 90 bottom
C539  0.1u/16V_4  [C0402]  60.39 104.38 270 bottom
C540  100p/50V_4  [C0402]  61.4 104.38 90 bottom
C541  180p/50V_4  [C0402]  56.2 103.82 270 bottom
C542  0.1u/16V_4  [C0402]  57.54 103.24 180 bottom
C543  EV@22u/6.3V_6  [C0603]  119.44 103.11 90 bottom
C544  *EV@22U/6.3V_6  [C0603]  121.09 103.11 90 bottom
C545  1u/6.3V_4  [C0402]  83.88 98.06 270 bottom
C546  EV@22u/6.3V_6  [C0603]  120.76 96.73 90 bottom
C547  EV@22u/6.3V_6  [C0603]  122.19 96.73 90 bottom
C548  *EV@22U/6.3V_6  [C0603]  123.61 96.73 90 bottom
C549  0.01u/50V_4  [C0402]  77.4 95.87 90 bottom
C550  10u/6.3V_4  [C0402]  78.42 95.87 90 bottom
C551  0.1u/16V_4  [C0402]  79.44 95.87 90 bottom
C552  10U/6.3V_6  [C0603]  62.01 94.25 90 bottom
C553  10U/6.3V_6  [C0603]  63.43 94.25 90 bottom
C554  EV@12p/50V_4  [C0402]  100.14 88.89 0 bottom
C555  EV@12p/50V_4  [C0402]  101.92 88.89 180 bottom
C556  10u/6.3V_4  [C0402_2]  84.67 84.87 270 bottom
C557  10u/6.3V_4  [C0402_2]  86.42 84.85 270 bottom
C558  HDMI_R@0.1u/16V_4  [C0402]  22.46 83.17 0 bottom
C559  *220p/50V_4  [C0402]  14.57 82.79 90 bottom
C560  HDMI_R@0.1u/16V_4  [C0402]  22.85 81.77 90 bottom
C561  HDMI_N@0.1u/10V_2  [C0201]  15.56 81.16 180 bottom
C562  HDMI_N@0.1u/10V_2  [C0201]  15.56 79.97 180 bottom
C563  *EV@22U/6.3V_6  [C0603]  134.05 79.74 180 bottom
C564  EV@22u/6.3V_6  [C0603]  137.09 79.74 180 bottom
C565  EV@1u/6.3V_4  [C0402]  130.9 79.64 270 bottom
C566  EV@1u/6.3V_4  [C0402]  131.86 79.64 270 bottom
C567  HDMI_N@0.1u/10V_2  [C0201]  15.56 79.26 180 bottom
C568  HDMI_N@0.1u/10V_2  [C0201]  15.56 78.07 180 bottom
C569  HDMI_N@0.1u/10V_2  [C0201]  15.56 77.35 180 bottom
C570  HDMI_N@0.1u/10V_2  [C0201]  15.56 76.16 180 bottom
C571  HDMI_N@0.1u/10V_2  [C0201]  15.56 75.45 180 bottom
C572  HDMI_N@0.1u/10V_2  [C0201]  15.56 74.26 180 bottom
C573  10u/6.3V_4  [C0402]  63.05 69.58 180 bottom
C574  10u/6.3V_4  [C0402]  63.05 68.57 180 bottom
C575  1U/6.3V_4  [C0402]  63.05 67.55 0 bottom
C576  *15P/25V_2  [C0201]  102.04 66.53 90 bottom
C577  1u/6.3V_4  [C0402]  63.05 66.41 180 bottom
C578  0.1u/16V_4  [C0402]  113.65 65.65 90 bottom
C579  1u/6.3V_4  [C0402]  63.05 65.26 180 bottom
C580  0.1u/6.3V_2  [C0201]  113.65 64.38 0 bottom
C581  10u/6.3V_4  [C0402]  63.05 64.12 180 bottom
C582  0.1u/6.3V_2  [C0201]  108.62 63.87 270 bottom
C583  0.1u/6.3V_2  [C0201]  109.33 63.87 270 bottom
C584  *1U/6.3V_4  [C0402]  63.05 63.11 0 bottom
C585  *10u/6.3V_4  [C0402_2]  104.3 62.85 0 bottom
C586  0.1u/16V_4  [C0402]  105.68 62.72 90 bottom
C587  *10u/6.3V_4  [C0402_2]  112.58 62.47 180 bottom
C588  1U/6.3V_4  [C0402]  101.19 61.14 270 bottom
C589  1U/6.3V_4  [C0402]  102.18 61.14 90 bottom
C590  0.1u/6.3V_2  [C0201]  103.21 60.06 270 bottom
C591  1U/6.3V_4  [C0402]  101.29 58.88 270 bottom
C592  1U/6.3V_4  [C0402]  102.3 58.88 90 bottom
C593  0.1u/16V_4  [C0402]  17.84 57.26 0 bottom
C594  1u/6.3V_4  [C0402]  63.41 56.09 180 bottom
C595  1U/6.3V_4  [C0402]  101.54 55.35 270 bottom
C596  1U/6.3V_4  [C0402]  63.43 55.05 0 bottom
C597  0.1u/6.3V_2  [C0201]  112.53 54.01 90 bottom
C598  1U/6.3V_4  [C0402]  101.54 53.44 270 bottom
C599  TPC@100u/6.3V_12  [C1206]  18.86 53.07 0 bottom
C600  *1000p/50V_4  [C0402]  108.9 50.91 0 bottom
C601  *10P/50V_2  [C0201]  102.78 50.84 90 bottom
C602  10U/10V_4  [C0402_2]  101.36 46.54 270 bottom
C603  0.1u/16V_4  [C0402]  105.37 45.5 180 bottom
C604  0.1u/16V_4  [C0402]  14.92 45.45 180 bottom
C605  *1000p/50V_4  [C0402]  109.59 45.27 270 bottom
C606  0.1u/16V_4  [C0402]  107.91 45.15 270 bottom
C607  *1000p/50V_4  [C0402]  106.77 45.12 270 bottom
C608  470p/50V_4  [C0402]  14.92 44.44 180 bottom
C609  0.1u/16V_4  [C0402]  14.92 43.42 180 bottom
C610  1u/6.3V_4  [C0402]  22.77 43.42 270 bottom
C611  0.1u/16V_2  [C0201]  102.42 41.77 0 bottom
C612  100u/6.3V_12  [C1206]  18.98 41.39 0 bottom
C613  0.1u/16V_2  [C0201]  102.42 41.01 0 bottom
C614  0.22u/10V_2  [C0201]  101.66 40.25 0 bottom
C615  1u/10V_6  [C0603]  207.99 39.97 180 bottom
C616  2.2u/6.3V_4  [C0402]  204.13 39.76 90 bottom
C617  0.22u/10V_2  [C0201]  101.66 39.48 0 bottom
C618  0.22u/10V_2  [C0201]  101.66 38.72 0 bottom
C619  10u/6.3V_4  [C0402_2]  210.02 38.44 270 bottom
C620  10u/6.3V_4  [C0402_2]  202.07 38.37 270 bottom
C621  0.22u/10V_2  [C0201]  101.66 37.96 0 bottom
C622  1u/10V_6  [C0603]  206.67 37.93 270 bottom
C623  0.1u/16V_4  [C0402]  200.98 37.71 270 bottom
C624  10u/6.3V_6  [C0603]  208.09 37.25 270 bottom
C625  0.22u/10V_2  [C0201]  101.66 37.2 180 bottom
C626  18p/50V_4  [C0402]  66.48 37.07 90 bottom
C627  10u/6.3V_4  [C0402_2]  199.63 37.07 0 bottom
C628  0.22u/10V_2  [C0201]  101.66 36.44 180 bottom
C629  10u/6.3V_4  [C0402_2]  209.51 36.18 90 bottom
C630  0.22u/10V_2  [C0201]  101.66 35.67 180 bottom
C631  0.22u/10V_2  [C0201]  101.66 34.91 180 bottom
C632  18p/50V_4  [C0402]  67.24 34.4 270 bottom
C633  *1U/6.3V_4  [C0402]  102.42 33.64 0 bottom
C634  *0.1u/16V_4  [C0402]  107.99 33.64 90 bottom
C635  10u/6.3V_4  [C0402_2]  199.15 33.41 0 bottom
C636  *0.1u/16V_4  [C0402]  102.42 32.63 0 bottom
C637  0.1u/16V_4  [C0402]  210.88 32.63 180 bottom
C638  256@0.1u/16V_4  [C0402]  197.55 32.32 0 bottom
C639  *10P/50V_2  [C0201]  108.77 32.12 270 bottom
C640  0.1U/10V_2  [C0201]  104.33 31.86 270 bottom
C641  10u/6.3V_4  [C0402_2]  210.88 31.48 180 bottom
C642  0.1U/10V_2  [C0201]  70.55 31.36 90 bottom
C643  *0.1u/16V_4  [C0402]  197.52 31.36 0 bottom
C644  *0.1u/16V_2  [C0201]  192.62 30.44 90 bottom
C645  0.1u/16V_2  [C0201]  193.33 30.44 90 bottom
C646  10u/6.3V_4  [C0402_2]  194.55 30.42 180 bottom
C647  0.1u/16V_4  [C0402]  210.73 30.39 180 bottom
C648  100p/50V_4  [C0402]  196.99 29.83 270 bottom
C649  *0.01U/50V_4  [C0402]  66.61 29.7 0 bottom
C650  10u/6.3V_4  [C0402_2]  210.65 29.3 180 bottom
C651  47U/6.3V_6  [C0603]  91.53 29.27 0 bottom
C652  2.2U/10V_4  [C0402]  80.17 29.07 270 bottom
C653  4.7U/6.3V_4  [C0402_2]  85.28 29.07 90 bottom
C654  0.1u/16V_2  [C0201]  93.31 29.07 90 bottom
C655  1u/6.3V_2  [C0201]  103.95 28.38 0 bottom
C656  0.1u/16V_4  [C0402]  209.13 28.18 270 bottom
C657  10P/50V_4  [C0402]  97.98 27.74 180 bottom
C658  10P/50V_4  [C0402]  99.76 27.74 0 bottom
C659  10u/6.3V_4  [C0402_2]  204.23 27.57 90 bottom
C660  255@0.1u/16V_4  [C0402]  200.16 27.32 270 bottom
C661  0.1u/16V_4  [C0402]  202.42 27.32 90 bottom
C662  *1U/6.3V_4  [C0402]  65.21 27.04 90 bottom
C663  33p/50V_4  [C0402]  208.49 26.78 0 bottom
C664  1u/10V_2  [C0201]  63.61 26.66 270 bottom
C665  0.1U/10V_2  [C0201]  64.35 26.66 270 bottom
C666  10u/6.3V_4  [C0402_2]  211.42 26.66 180 bottom
C667  *22p/50V_4  [C0402]  204.56 26.05 0 bottom
C668  TPC@0.1u/16V_4  [C0402]  17.59 25.26 90 bottom
C669  TPC@0.1u/16V_4  [C0402]  18.6 25.26 90 bottom
C670  *22U/6.3V_6  [C0603]  209.1 24.98 270 bottom
C671  *100u/6.3V_12  [C1206]  206.08 24.27 180 bottom
C672  470p/50V_4  [C0402]  210.3 23.46 270 bottom
C673  0.1u/16V_4  [C0402]  211.26 23.35 270 bottom
C674  *0.1u/16V_4  [C0402]  212.23 23.33 270 bottom
C675  TPC@0.1u/16V_4  [C0402]  21.2 23.26 180 bottom
C676  0.1u/10V_2  [C0201]  171.77 22.97 90 bottom
C677  0.1u/16V_2  [C0201]  180.78 22.95 90 bottom
C678  0.1u/16V_2  [C0201]  181.49 22.95 90 bottom
C679  0.1u/10V_2  [C0201]  180.05 22.64 270 bottom
C680  10P/50V_4  [C0402]  73.21 22.34 270 bottom
C681  10P/50V_4  [C0402]  74.33 22.34 270 bottom
C682  0.1u/16V_4  [C0402]  76.49 22.34 270 bottom
C683  *ODD@100u/6.3V_12  [C1206]  126.43 22.34 270 bottom
C684  TPC@0.1u/16V_4  [C0402]  21.2 22.25 180 bottom
C685  ODD@10u/6.3V_6  [C0603]  128.33 21.58 270 bottom
C686  *ODD@0.1u/16V_4  [C0402]  129.6 21.58 90 bottom
C687  *ODD@0.1u/16V_4  [C0402]  130.62 21.58 90 bottom
C688  ODD@0.01u/50V_4  [C0402]  131.63 21.58 90 bottom
C689  ODD@0.01u/50V_4  [C0402]  132.65 21.58 90 bottom
C690  TPC@0.1u/16V_4  [C0402]  12.51 21.42 270 bottom
C691  TPC@0.1u/16V_4  [C0402]  13.47 21.42 270 bottom
C692  *TPC@0.1u/16V_4  [C0402]  14.44 21.42 270 bottom
C693  ODD@0.01u/50V_4  [C0402]  136.13 21.32 270 bottom
C694  ODD@0.01u/50V_4  [C0402]  137.09 21.32 270 bottom
C695  TPC@0.1u/16V_4  [C0402]  21.55 21.2 180 bottom
C696  ODD@0.01u/50V_4  [C0402]  133.64 21.2 270 bottom
C697  ODD@0.01u/50V_4  [C0402]  134.61 21.2 270 bottom
C698  1u/6.3V_4  [C0402]  203.72 21.07 90 bottom
C699  *ODD@15p/50V_4  [C0402]  138.49 20.69 270 bottom
C700  TPC@0.1u/16V_4  [C0402]  21.55 20.18 180 bottom
C701  TPC@0.1u/16V_4  [C0402]  14.67 19.54 270 bottom
C702  TPC@0.1u/16V_4  [C0402]  15.68 19.54 270 bottom
C703  ODD@180p/50V_4  [C0402]  139.13 19.16 0 bottom
C704  TPC@47u/6.3V_8  [C0805]  29.25 19.04 270 bottom
C705  *KBL@2.2u/6.3V_6  [C0603]  197.83 17.82 90 bottom
C706  TPC@150u/6.3V_3528H1.4  [C3528]  18.35 14.77 90 bottom
C707  0.1u/16V_2  [C0201]  181.16 14.72 0 bottom
C708  *TPC@47u/6.3V_8  [C0805]  30.14 14.64 90 bottom
C709  TPC@10u/25V_8  [C0805]  21.37 14.59 270 bottom
C710  TPC@22u/6.3V_6  [C0603]  27.87 14.34 90 bottom
C711  *TPC@390p/50V_4  [C0402]  10.22 13.45 270 bottom
C712  *0.1u/16V_2  [C0201]  21.02 11.67 0 bottom
C713  KBL@0.01u/50V_4  [C0402]  198.56 11.54 270 bottom
C714  KBL@4.7u/6.3V_6  [C0603]  197.29 11.42 270 bottom
C715  0.1u/16V_2  [C0201]  192.31 10.98 270 bottom
C716  0.1u/16V_2  [C0201]  193.2 10.98 270 bottom
C717  *0.1u/16V_2  [C0201]  193.97 10.98 270 bottom
C718  *0.1u/16V_2  [C0201]  194.73 10.98 270 bottom
C719  10u/6.3V_4  [C0402_2]  195.74 10.98 270 bottom
C720  1u/6.3V_2  [C0201]  14.16 10.81 180 bottom
C721  1u/6.3V_2  [C0201]  14.16 10.1 180 bottom
C722  1u/6.3V_2  [C0201]  15.17 9.38 180 bottom
C723  *0.1U/10V_2  [C0201]  66.51 35.42 270 top
C724  *0.1U/10V_2  [C0201]  66.31 30.21 0 top
C725  *0.1u/10V_2  [C0201]  97.46 84.39 0 bottom
C726  *0.1u/10V_2  [C0201]  101.76 50.43 90 bottom
CN1  *50208-00401-V02  [50208-00401-V02-4P-L]  35.1 118.05 0 bottom
CN2  196538-40041-3  [196538-40041-3-40P-L]  53.6 110.3 0 bottom
CN3  2RJ1622-001111F  [RJ45-2RJ1622-001111F-8P]  10.05 96.2 90 bottom
CN4  10444-19001  [HDMI-10591-19001-19P]  3.4 76.2 90 bottom
CN5  USB3.0 CONN  [UB3-USB-097-1R09HG-9P]  7.4 54.44 90 bottom
CN6  51619-04001-V04  [51619-04001-V04-40P-L]  216.25 38.15 270 bottom
CN7  USB3.0 CONN  [UB3-USB-097-1R09HG-9P]  7.4 34.44 90 bottom
CN8  FOR14@196153-28021-35  [50584-0280N-V02-28P-L]  139.9 23.2 180 bottom
CN9  NASE0-S6701-TS40  [NGFF-NASE0-S6701-TS40-KE-SMT]  188.5 21.88 270 bottom
CN10  FOR15_17@196153-28021-35  [50584-0280N-V02-28P-L]  161.5 18.5 180 bottom
CN11  51325-00401-001  [51325-00401-001-4P-L]  117.8 17.6 180 bottom
CN12  51653-0080N-V02  [196047-08021-3-8P-L]  72.82 17.55 180 bottom
CN13  PBA@196241-08021-3  [196241-08021-3-8P-L]  58.7 17.17 180 bottom
CN14  UCF3M-01N01-0P53  [UB31-UCF3M-01N01-0P53-24P]  7.26 15.9 90 bottom
CN15  ODD@132F18-100000-A2-R  [132F18-100000-A2-R-18P-L]  132.6 14.35 180 bottom
CN16  KBL@50505-00401-v01-4p-l  [50505-00401-V01-4P-L]  204.32 10.95 180 bottom
CN17  51614-00601-V01  [51614-00601-V01-6P-L]  45.7 8.74 180 bottom
CN18  SSD@NASM0-S6701-TSH4  [NGFF-NASM0-S6701-TSH4-KM-SMT]  30.6 4.35 180 bottom
CN19  50281-00201-001  [50281-00201-001-2P-L]  14.3 3.45 180 bottom
D1  1N4148WS  [D-SOD323-1_85X1_25-0_95H]  53.55 103.75 270 top
D2  EV@RB500V-40  [D-SOD323-1_85X1_25-0_95H]  86.85 100.57 0 top
D3  *PESD5V0H1BSF  [D-0_6X0_3-0_32H-SMT]  14.41 82.94 180 top
D4  *PESD5V0H1BSF  [D-0_6X0_3-0_32H-SMT]  15.71 82.28 180 top
D5  BAT54AW-L  [SOT23-1_7-65-3P]  23.94 71.49 270 top
D6  *RB500V-40  [D-SOD323-1_85X1_25-0_95H]  109.54 48.88 180 top
D7  *RB500V-40  [D-SOD323-1_85X1_25-0_95H]  111.44 44.06 180 top
D8  *RB500V-40  [D-SOD323-1_85X1_25-0_95H]  167.19 31.99 0 top
D9  *RB500V-40  [D-SOD323-1_85X1_25-0_95H]  169.78 30.85 270 top
D10  TVM0G5R5M220R_22p  [R0402]  183.32 29.58 270 top
D11  *RB500V-40  [D-SOD323-1_85X1_25-0_95H]  167.32 29.2 0 top
D12  *RB500V-40  [D-SOD323-1_85X1_25-0_95H]  167.32 27.8 0 top
D13  RB500V-40  [D-SOD323-1_85X1_25-0_95H]  175.6 25.92 0 top
D14  GS@RB500V-40  [D-SOD323-1_85X1_25-0_95H]  60.89 21.83 0 top
D15  GS@RB500V-40  [D-SOD323-1_85X1_25-0_95H]  64.7 21.83 180 top
D16  *TPM@PESD5V0F1BL  [R0402]  130.08 19.47 180 top
D17  AZ5725-01F.R7G  [ESD-1X0_6-2P]  150.56 18.4 90 top
D18  *VPORT_0603_220K-V05  [R0603]  149.67 16.75 180 top
D19  TPC@EGA10402V05AH_0.2p  [R0402]  11.62 13.65 0 top
D20  TPC@PDZ5.6B  [D-SOD323-1_7X1_25-PMEG4005AEA]  18.6 11.29 90 top
D21  *VPORT_0603_220K-V05  [R0603]  38.54 121.53 270 bottom
D22  *VPORT_0603_220K-V05  [R0603]  40.83 120.61 90 bottom
D23  *RB500V-40  [D-1_85X1_25-2P-0_95H]  104.63 85.18 180 bottom
D24  *AZ5725-01F.R7G  [ESD-1X0_6-2P]  15.56 82.79 90 bottom
